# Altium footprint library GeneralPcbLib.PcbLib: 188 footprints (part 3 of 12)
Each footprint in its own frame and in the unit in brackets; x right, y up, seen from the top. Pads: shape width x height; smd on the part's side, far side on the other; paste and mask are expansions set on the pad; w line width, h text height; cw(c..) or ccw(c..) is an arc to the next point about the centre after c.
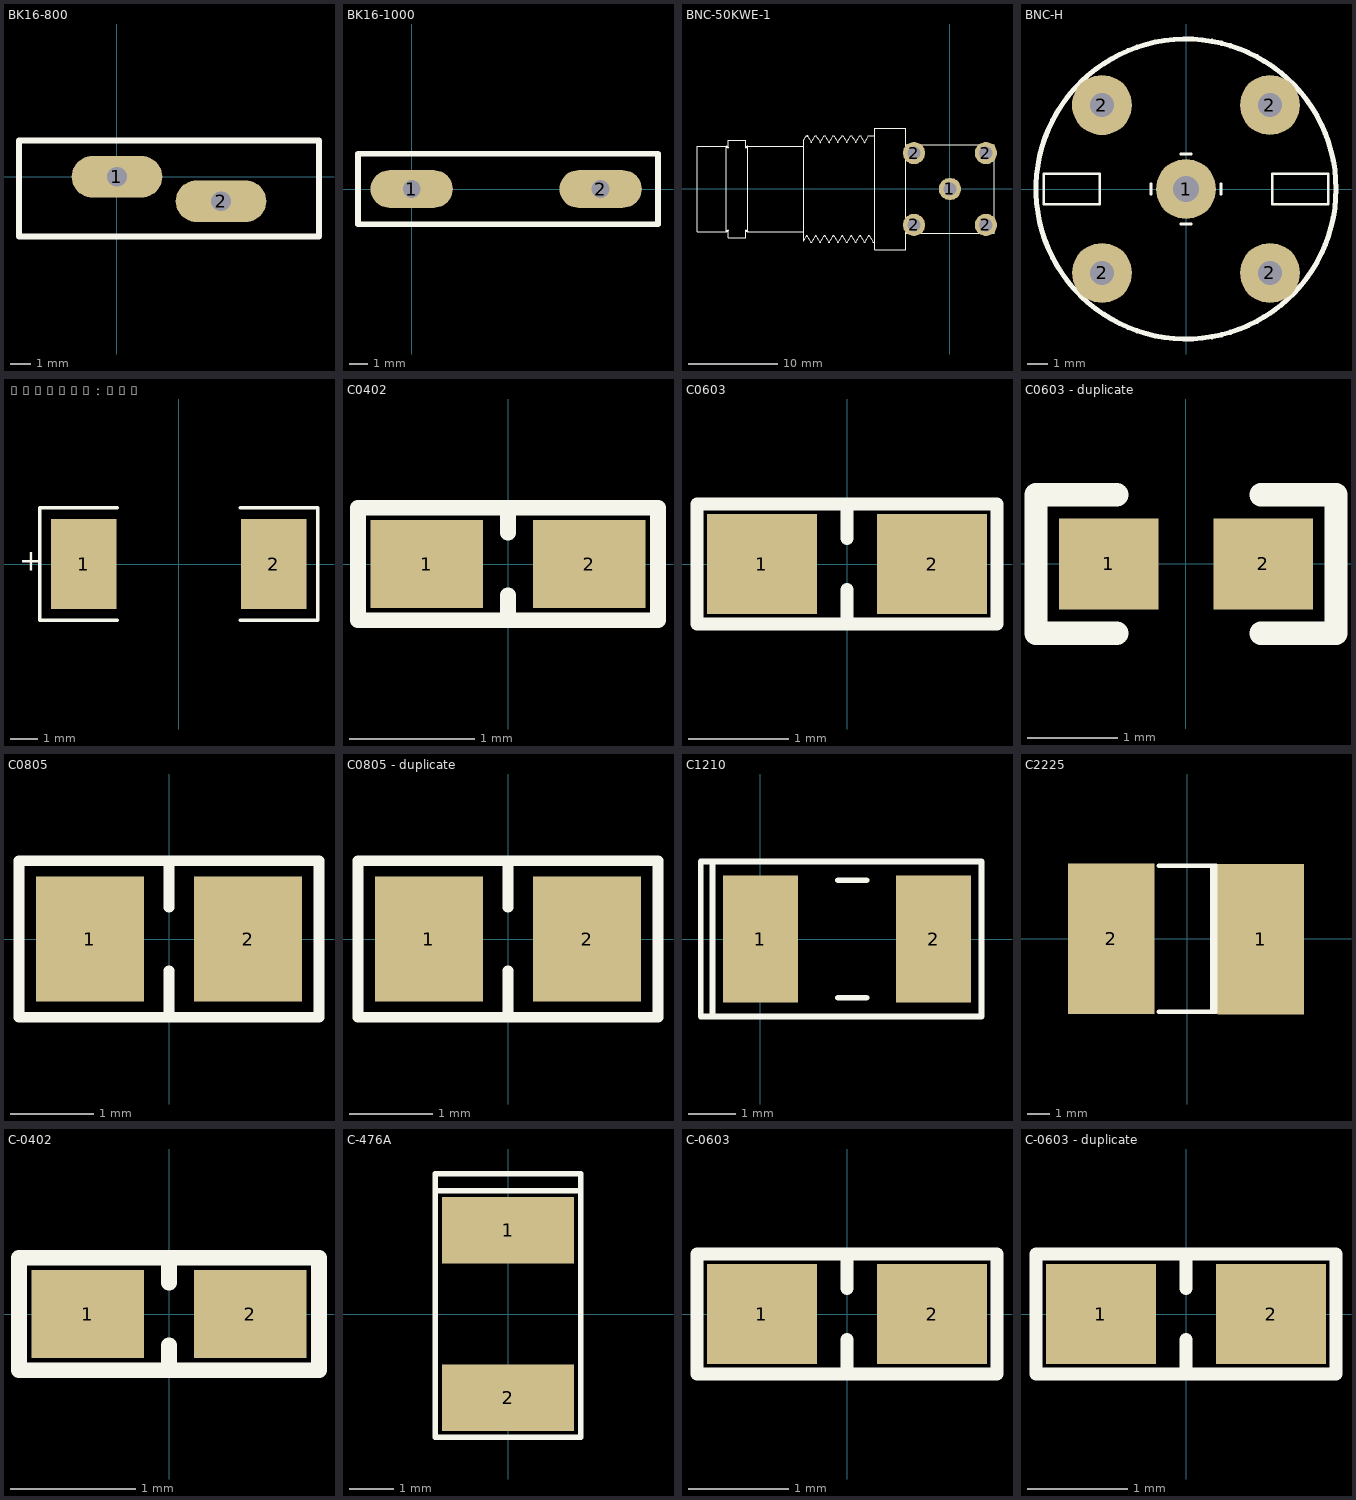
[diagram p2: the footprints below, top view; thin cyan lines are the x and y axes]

## BK16-800 [mm] "自恢复保险丝"
height 15
pads (2):
  oval 4.445x2.032 hole 0.965: 1(0,0) 2(5.1,-1.2)
Top Overlay:
  lines w0.305: -4.8,-2.921 9.9,-2.921 9.9,1.778 -4.8,1.778 -4.8,-2.921

## BK16-1000 [mil] "自恢复保险丝"
height 590.55
pads (2):
  oval 175x80 hole 38: 1(0,0) 2(401.57,0)
Top Overlay:
  lines w12: -114.17,-75 523.62,-75 523.62,75 -114.17,75 -114.17,-75

## BNC-50KWE-1 [mm] "库房BNC-KWE-1"
height 14
pads (5):
  round 2.5 hole 1.5: 1(0,0) 2(-4.05,-4.05) 2(-4.05,4.05) 2(4.05,-4.05) 2(4.05,4.05)
Top Overlay:
  drawing of 401 lines, arcs and shapes, not listed

## BNC-H [mm] "立式BNC"
pads (5):
  round 3 hole 1.3: 1(0,0)
  round 3 hole 1.2: 2(-4.2,4.2) 2(-4.2,-4.2) 2(4.2,-4.2) 2(4.2,4.2)
Top Overlay:
  circle w0.254: c0,0 r7.5
  lines w0.127: -1.75,-0.27 -1.75,0.27 ; -0.27,-1.75 0.27,-1.75 ; -0.27,1.75 0.27,1.75 ; 1.75,-0.27 1.75,0.27 ; -7.112,-0.762 -7.112,0.762 -6.858,0.762 -4.318,0.762 -4.318,-0.762 -7.112,-0.762 ; 4.318,-0.762 7.112,-0.762 7.112,0.762 5.588,0.762 4.318,0.762 4.318,-0.762

## C3.5-95：SMC [mm] "大型号电容，107A，477J,686等"
height 5
pads (2):
  rect 2.4x3.3 smd: 1(-3.475,0) 2(3.475,0)
Top Overlay:
  lines w0.127: -2.248,-2.05 -5.075,-2.05 -5.075,2.05 -2.248,2.05 ; 2.248,-2.05 5.075,-2.05 5.075,2.05 2.248,2.05
  text "+" at -5.842,-0.254 h0.76

## C0402 [mm]
pads (2):
  rect 0.9x0.7 smd: 1(-0.65,0) 2(0.65,0)
Top Overlay:
  lines w0.127: 0,-0.45 0,-0.25 ; 0,0.25 0,0.45 ; -1.2,-0.45 -1.2,0.45 1.2,0.45 1.2,-0.45 -1.2,-0.45
3D body: height 0.3, standoff 0, extent 0.508,-0.254 1.016,0.254
3D body: height 0.3, standoff 0, extent -1.016,-0.254 -0.508,0.254

## C0603 [mm]
pads (2):
  rect 1.1x1 smd: 1(-0.85,0) 2(0.85,0)
Top Overlay:
  lines w0.127: 0,-0.6 0,-0.254 ; 0,0.254 0,0.6 ; -1.5,-0.6 1.5,-0.6 1.5,0.6 -1.5,0.6 -1.5,-0.6

## C0603 - duplicate [mm]
height 1.35
pads (2):
  rect 1.1x1 smd: 1(-0.85,0) 2(0.85,0)
Top Overlay:
  lines w0.254: -0.762,-0.762 -1.651,-0.762 -1.651,0.762 -0.762,0.762 ; 0.826,-0.762 1.651,-0.762 1.651,0.762 0.826,0.762

## C0805 [mm]
pads (2):
  rect 1.3x1.5 smd: 1(-0.95,0) 2(0.95,0)
Top Overlay:
  lines w0.127: 0,-0.94 0,-0.381 ; 0,0.381 0,0.889 ; -1.803,-0.94 1.803,-0.94 1.803,0.94 -1.803,0.94 -1.803,-0.94

## C0805 - duplicate [mm]
pads (2):
  rect 1.3x1.5 smd: 1(-0.95,0) 2(0.95,0)
Top Overlay:
  lines w0.127: 0,-0.94 0,-0.381 ; 0,0.381 0,0.889 ; -1.803,-0.94 -1.803,0.94 1.803,0.94 1.803,-0.94 -1.803,-0.94

## C1210 [mm]
pads (2):
  rect 1.6x2.7 smd: 1(0,0) 2(3.683,0)
Top Overlay:
  lines w0.127: 1.654,-1.25 2.254,-1.25 ; 1.654,1.25 2.254,1.25 ; -1.016,-1.651 -1.27,-1.651 -1.27,1.651 -1.016,1.651 ; -1.016,-1.651 4.699,-1.651 4.699,1.651 -1.016,1.651 ; -1.016,-1.651 -1.016,1.651

## C2225 [mm] "Chip Capacitor; Body 5.6 x 6.4 mm (LxW typ)"
height 1.1
pads (2):
  rect 3.9x6.8 smd: 1(3.302,-0.025) 2(-3.429,0)
Top Overlay:
  lines w0.2: -1.3,-3.3 1.3,-3.3 1.3,3.3 -1.3,3.3 ; 1.11,-3.3 1.11,3.3
3D body: height 4.5, standoff -0.01, extent -2.857,-2.6 2.857,2.6

## C-0402 [mm]
pads (2):
  rect 0.9x0.7 smd: 1(-0.65,0) 2(0.65,0)
Top Overlay:
  lines w0.127: 0,-0.45 0,-0.25 ; 0,0.25 0,0.45 ; -1.2,-0.45 1.2,-0.45 1.2,0.45 -1.2,0.45 -1.2,-0.45
3D body: height 0.3, standoff 0, extent -1.016,-0.254 -0.508,0.254
3D body: height 0.3, standoff 0, extent 0.508,-0.254 1.016,0.254

## C-476A [mm]
pads (2):
  rect 3x1.5 smd: 1(0,1.9) 2(0,-1.9)
Top Overlay:
  lines w0.127: -1.651,2.794 1.651,2.794 ; -1.651,-2.794 1.651,-2.794 1.651,3.175 -1.651,3.175 -1.651,-2.794

## C-0603 [mm]
height 0.5
pads (2):
  rect 1.1x1 smd: 1(-0.85,0) 2(0.85,0)
Top Overlay:
  lines w0.127: 0,-0.6 0,-0.254 ; 0,0.254 0,0.6 ; -1.5,-0.6 -1.5,0.6 1.5,0.6 1.5,-0.6 -1.5,-0.6
3D body: height 0.5, standoff 0, extent -1.35,-0.45 1.35,0.45

## C-0603 - duplicate [mm]
height 0.5
pads (2):
  rect 1.1x1 smd: 1(-0.85,0) 2(0.85,0)
Top Overlay:
  lines w0.127: 0,-0.6 0,-0.254 ; 0,0.254 0,0.6 ; -1.5,-0.6 1.5,-0.6 1.5,0.6 -1.5,0.6 -1.5,-0.6
3D body: height 0.5, standoff 0, extent -1.35,-0.45 1.35,0.45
